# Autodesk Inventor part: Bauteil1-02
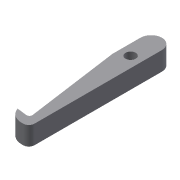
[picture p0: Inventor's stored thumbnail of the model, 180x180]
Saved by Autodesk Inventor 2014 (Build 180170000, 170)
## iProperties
Company: VDW-Nachwuchsstiftung
Created: 2014-03
Part Number: Bauteil1-02
Material: Generisch
Document SubType Name: Modeling
Designer: e_dammj
Density: 1 g/cm^3
Appearance: Vorgabe
Author: e_dammj
Title: Abziehhebel
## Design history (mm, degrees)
sketch "Skizze1"
  geometry: L1 (5.75, 0)-(5.75, -68.25); L2 (-5.75, 0)-(-5.75, -15); L3 (-0.433, -66.401)-(-5.75, -65.748); L4 (1.85, -71.25)-(2.75, -71.25); L5 (-5.75, -15)-(1.235, -64.704); A1 r 5.75 centre (0, 0) between (5.75, 0) and (-5.75, 0); A2 r 8 centre (1.85, -63.25) between (-5.75, -65.748) and (1.85, -71.25); A3 r 1.5 centre (-0.25, -64.912) between (-0.433, -66.401) and (1.235, -64.704); A4 r 3 centre (2.75, -68.25) between (2.75, -71.25) and (5.75, -68.25); 2 further points
  constraints: 10 end point, 8 point on circle, 7 tangent, 4 centre point, 2 point on line, 1 coincident, 1 parallel, 1 perpendicular, 1 vertical
  dimensions: "d0" = 5.75 radius of A1; "d6" = 11.5 distance from line of L1 L3.end; "d8" = 8 radius of A2; "d9" = 8 deg angle of L5 L2; "d10" = 75 deg angle of L3 L5; "d11" = 1.5 radius of A3; "d12" = 6 distance from line of L1 A3.centre; "d13" = 3 radius of A4; "d25" = 77 dimension on A1 L4; "d26" = 15 vertical distance of A1.centre L2.end
extrude "Extrusion1" new body sketch "Skizze1" stored distance "d14" = 10; taper "d15" = 0 deg
sketch "Skizze2"
  geometry: A1 r 5.75 centre (0, 0) between (5.75, 0) and (-5.75, 0) reference; 1 further point
  dimensions: "d16" = 11 distance of A1.centre point (0, -11)
hole "Bohrung1" sketch "Skizze2" at (0, -11) diameter "d17" = 5.5; stored, may be unused: countersink angle "d21" = 90 deg, drill point angle "d23" = 118 deg; dims "d18" = 6, "d19" = 4, "d20" = 2, "d22" = 8
node "Volumenkörper1"
